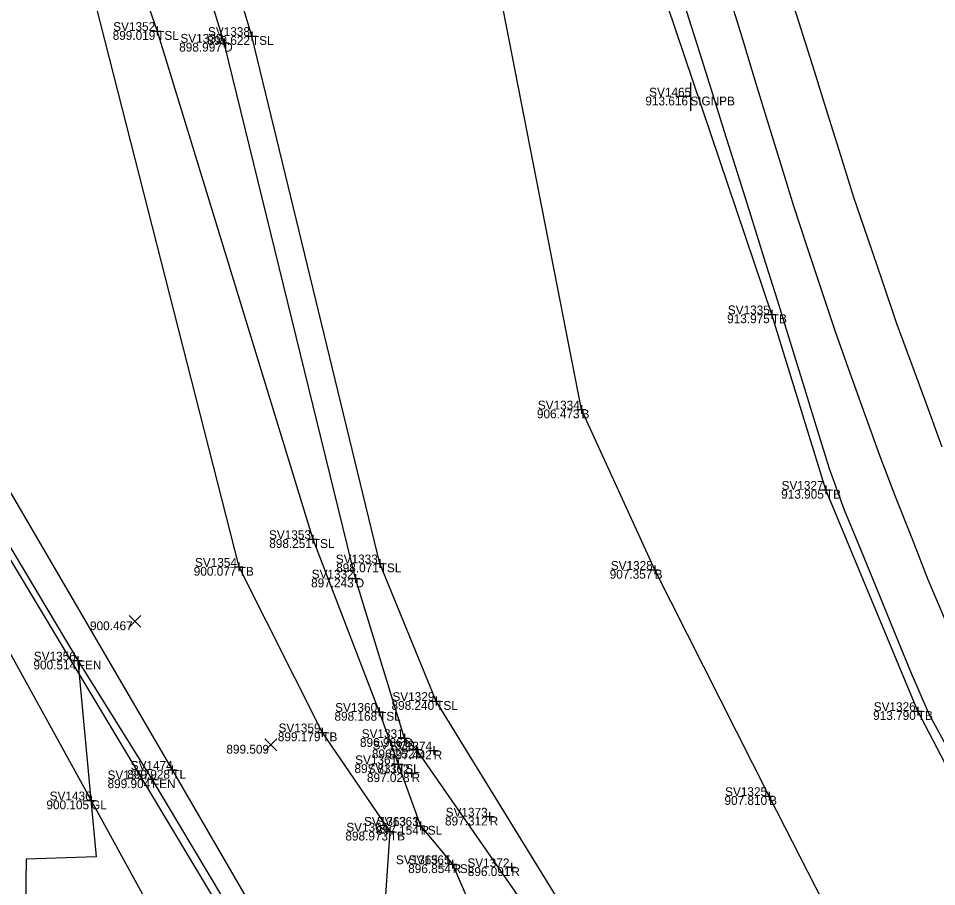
# Model space of a CAD drawing. Extents: x 1918148 to 1919797, y 624701 to 627089.
# Drawn here: x 1918830.7 to 1918934.8, y 625607.8 to 625706.2 of the extents above; entities that cross this region are included whole.
import ezdxf

# ---------------------------------------------------------------- set-up
doc = ezdxf.new("R2010")
doc.units = 0
for name, color, linetype in [('DR_X_Ditch', 7, 'Continuous'), ('DT_X_Terrain_Boundary', 7, 'Continuous'), ('Ground Shots', 7, 'Continuous'), ('PM_X_Edge_Line', 7, 'Continuous'), ('PV_X_Shoulder_Aggregate', 7, 'Continuous'), ('RD_X_Concrete_Pad', 7, 'Continuous'), ('RD_X_Fence', 7, 'Continuous'), ('SN_X_Public', 7, 'Continuous'), ('SV_X_Break_Lines', 7, 'Continuous'), ('SV_X_Random_Point', 7, 'Continuous'), ('SV_X_Shot_Marker', 7, 'Continuous'), ('SV_X_Text_Comment', 7, 'Continuous'), ('SV_X_Text_Elevation', 7, 'Continuous'), ('SV_X_Text_Name', 7, 'Continuous'), ('SV_X_Toe_of_Slope', 7, 'Continuous'), ('SV_X_Top_of_Bank', 7, 'Continuous'), ('UT_X_Gas', 7, 'Continuous'), ('UT_X_Overhead_Combined', 7, 'Continuous'), ('UT_X_Telecom', 7, 'Continuous')]:
    doc.layers.add(name, color=color, linetype=linetype)

msp = doc.modelspace()

# ---------------------------------------------------------------- linework, layer by layer
at = {"layer": 'DR_X_Ditch'}
msp.add_lwpolyline([(1918900.32, 625584.27), (1918896.98, 625591.92), (1918892.59, 625599.25), (1918875.81, 625623.37), (1918874.46, 625624.66), (1918868.91, 625642.74), (1918854.01, 625703.44), (1918836.26, 625761.36)], dxfattribs=at)
at = {"layer": 'DT_X_Terrain_Boundary'}
msp.add_lwpolyline([(1918796.76, 625701.53), (1918837.42, 625633.44), (1918839.5, 625611.2), (1918831.56, 625610.96), (1918831.45, 625603.21), (1918831.49, 625595.21), (1918831.79, 625587.3), (1918839.47, 625579.2), (1918839.49, 625571.21), (1918847.48, 625555.19), (1918855.45, 625539.21), (1918863.74, 625523.31), (1918871.72, 625515.38), (1918879.45, 625499.23)], dxfattribs=at)
at = {"layer": 'Ground Shots'}
for p, q in [((1918839.5, 625611.2), (1918839.5, 625611.2)), ((1918831.56, 625610.96), (1918831.56, 625610.96))]:
    msp.add_line(p, q, dxfattribs=at)
at = {"layer": 'PM_X_Edge_Line'}
msp.add_lwpolyline([(1918917.87, 625709.8), (1918919.37, 625705.03), (1918920.87, 625700.26), (1918922.36, 625695.49), (1918923.86, 625690.71), (1918925.36, 625685.95), (1918926.97, 625681.21), (1918928.58, 625676.48), (1918930.2, 625671.75), (1918931.92, 625667.05), (1918933.64, 625662.36), (1918935.37, 625657.67)], dxfattribs=at)
at = {"layer": 'PV_X_Shoulder_Aggregate'}
msp.add_lwpolyline([(1918936.29, 625622.98), (1918933.92, 625627.38), (1918931.93, 625631.97), (1918930.04, 625636.59), (1918928.14, 625641.22), (1918926.24, 625645.84), (1918924.34, 625650.47), (1918922.62, 625655.16), (1918921.15, 625659.94), (1918919.67, 625664.71), (1918918.2, 625669.49), (1918916.72, 625674.27), (1918915.23, 625679.04), (1918913.73, 625683.81), (1918912.23, 625688.58), (1918910.73, 625693.35), (1918909.24, 625698.12), (1918907.74, 625702.89), (1918906.24, 625707.66)], dxfattribs=at)
at = {"layer": 'RD_X_Concrete_Pad'}
msp.add_lwpolyline([(1918911.23, 625708.88), (1918912.67, 625704.1), (1918914.12, 625699.31), (1918915.59, 625694.53), (1918917.07, 625689.75), (1918918.55, 625684.98), (1918920.11, 625680.23), (1918921.69, 625675.49), (1918923.27, 625670.74), (1918924.94, 625666.03), (1918926.63, 625661.32), (1918928.32, 625656.62), (1918930.11, 625651.95), (1918931.94, 625647.3), (1918933.77, 625642.64), (1918935.73, 625638.04)], dxfattribs=at)
at = {"layer": 'RD_X_Fence'}
msp.add_lwpolyline([(1918745.79, 625786.43), (1918772.78, 625741.75), (1918796.76, 625701.53), (1918837.42, 625633.44), (1918845.82, 625619.99), (1919000.61, 625360.91)], dxfattribs=at)
at = {"layer": 'SN_X_Public'}
for p, q in [((1918906.85, 625698.94), (1918906.85, 625695.74)), ((1918906.85, 625697.34), (1918905.25, 625697.34))]:
    msp.add_line(p, q, dxfattribs=at)
at = {"layer": 'SV_X_Break_Lines'}
msp.add_lwpolyline([(1919045.66, 625427.6), (1919011.53, 625464.07), (1918983.19, 625498.78), (1918965.77, 625524.18), (1918940.24, 625565.26), (1918931.64, 625587.04), (1918915.78, 625618.09), (1918902.81, 625643.72), (1918894.51, 625661.89), (1918884.61, 625712.49), (1918865.54, 625771.79)], dxfattribs=at)
at = {"layer": 'SV_X_Random_Point'}
for p, q in [((1918843.23, 625637.22), (1918844.57, 625638.56)), ((1918843.23, 625638.56), (1918844.57, 625637.22)), ((1918858.63, 625623.23), (1918859.97, 625624.57)), ((1918858.63, 625624.57), (1918859.97, 625623.23))]:
    msp.add_line(p, q, dxfattribs=at)
at = {"layer": 'SV_X_Shot_Marker'}
for p, q in [((1918845.91, 625704.77), (1918846.91, 625704.77)), ((1918846.41, 625705.27), (1918846.41, 625704.27)), ((1918846.41, 625704.77), (1918846.41, 625704.77)), ((1918854.01, 625703.94), (1918854.01, 625702.94)), ((1918856.66, 625704.2), (1918857.66, 625704.2)), ((1918857.16, 625704.7), (1918857.16, 625703.7)), ((1918857.16, 625704.2), (1918857.16, 625704.2)), ((1918853.51, 625703.44), (1918854.51, 625703.44)), ((1918854.01, 625703.44), (1918854.01, 625703.44)), ((1918915.59, 625672.67), (1918916.59, 625672.67)), ((1918916.09, 625673.17), (1918916.09, 625672.17)), ((1918916.09, 625672.67), (1918916.09, 625672.67)), ((1918894.51, 625662.39), (1918894.51, 625661.39)), ((1918894.01, 625661.89), (1918895.01, 625661.89)), ((1918894.51, 625661.89), (1918894.51, 625661.89)), ((1918921.72, 625652.79), (1918922.72, 625652.79)), ((1918922.22, 625653.29), (1918922.22, 625652.29)), ((1918922.22, 625652.79), (1918922.22, 625652.79)), ((1918864.06, 625647.7), (1918864.06, 625646.7)), ((1918863.56, 625647.2), (1918864.56, 625647.2)), ((1918864.06, 625647.2), (1918864.06, 625647.2)), ((1918855.66, 625644.56), (1918855.66, 625643.56)), ((1918871.14, 625644.45), (1918872.14, 625644.45)), ((1918871.64, 625644.95), (1918871.64, 625643.95)), ((1918871.64, 625644.45), (1918871.64, 625644.45)), ((1918855.16, 625644.06), (1918856.16, 625644.06)), ((1918855.66, 625644.06), (1918855.66, 625644.06)), ((1918902.31, 625643.72), (1918903.31, 625643.72)), ((1918902.81, 625644.22), (1918902.81, 625643.22)), ((1918902.81, 625643.72), (1918902.81, 625643.72)), ((1918868.41, 625642.74), (1918869.41, 625642.74)), ((1918868.91, 625643.24), (1918868.91, 625642.24)), ((1918868.91, 625642.74), (1918868.91, 625642.74)), ((1918837.42, 625633.94), (1918837.42, 625632.94)), ((1918836.92, 625633.44), (1918837.92, 625633.44)), ((1918837.42, 625633.44), (1918837.42, 625633.44)), ((1918877.54, 625628.86), (1918878.54, 625628.86)), ((1918878.04, 625629.36), (1918878.04, 625628.36)), ((1918878.04, 625628.86), (1918878.04, 625628.86)), ((1918871.57, 625628.13), (1918871.57, 625627.13)), ((1918932.13, 625627.72), (1918933.13, 625627.72)), ((1918932.63, 625628.22), (1918932.63, 625627.22)), ((1918932.63, 625627.72), (1918932.63, 625627.72)), ((1918871.07, 625627.63), (1918872.07, 625627.63)), ((1918871.57, 625627.63), (1918871.57, 625627.63)), ((1918865.13, 625625.81), (1918865.13, 625624.81)), ((1918864.63, 625625.31), (1918865.63, 625625.31)), ((1918865.13, 625625.31), (1918865.13, 625625.31)), ((1918873.96, 625624.66), (1918874.96, 625624.66)), ((1918874.46, 625625.16), (1918874.46, 625624.16)), ((1918874.46, 625624.66), (1918874.46, 625624.66)), ((1918875.81, 625623.87), (1918875.81, 625622.87)), ((1918877.76, 625623.75), (1918877.76, 625622.75)), ((1918875.31, 625623.37), (1918876.31, 625623.37)), ((1918875.81, 625623.37), (1918875.81, 625623.37)), ((1918877.26, 625623.25), (1918878.26, 625623.25)), ((1918877.76, 625623.25), (1918877.76, 625623.25)), ((1918848.13, 625621.56), (1918848.13, 625620.56)), ((1918873.22, 625621.7), (1918874.22, 625621.7)), ((1918873.72, 625622.2), (1918873.72, 625621.2)), ((1918873.72, 625621.7), (1918873.72, 625621.7)), ((1918845.82, 625620.49), (1918845.82, 625619.49)), ((1918847.63, 625621.06), (1918848.63, 625621.06)), ((1918848.13, 625621.06), (1918848.13, 625621.06)), ((1918874.75, 625620.68), (1918875.75, 625620.68)), ((1918875.25, 625621.18), (1918875.25, 625620.18)), ((1918875.25, 625620.68), (1918875.25, 625620.68)), ((1918845.32, 625619.99), (1918846.32, 625619.99)), ((1918845.82, 625619.99), (1918845.82, 625619.99)), ((1918915.78, 625618.59), (1918915.78, 625617.59)), ((1918838.43, 625617.6), (1918839.43, 625617.6)), ((1918838.93, 625618.1), (1918838.93, 625617.1)), ((1918838.93, 625617.6), (1918838.93, 625617.6)), ((1918915.28, 625618.09), (1918916.28, 625618.09)), ((1918915.78, 625618.09), (1918915.78, 625618.09)), ((1918884.1, 625616.26), (1918884.1, 625615.26)), ((1918876.27, 625615.22), (1918876.27, 625614.22)), ((1918876.27, 625615.22), (1918876.27, 625614.22)), ((1918883.6, 625615.76), (1918884.6, 625615.76)), ((1918884.1, 625615.76), (1918884.1, 625615.76)), ((1918872.8, 625614.56), (1918872.8, 625613.56)), ((1918875.77, 625614.72), (1918876.77, 625614.72)), ((1918875.77, 625614.72), (1918876.77, 625614.72)), ((1918876.27, 625614.72), (1918876.27, 625614.72)), ((1918876.27, 625614.72), (1918876.27, 625614.72)), ((1918872.3, 625614.06), (1918873.3, 625614.06)), ((1918872.8, 625614.06), (1918872.8, 625614.06)), ((1918879.4, 625610.37), (1918880.4, 625610.37)), ((1918879.4, 625610.37), (1918880.4, 625610.37)), ((1918879.9, 625610.87), (1918879.9, 625609.87)), ((1918879.9, 625610.87), (1918879.9, 625609.87)), ((1918879.9, 625610.37), (1918879.9, 625610.37)), ((1918879.9, 625610.37), (1918879.9, 625610.37)), ((1918886.06, 625610.03), (1918887.06, 625610.03)), ((1918886.56, 625610.53), (1918886.56, 625609.53)), ((1918886.56, 625610.03), (1918886.56, 625610.03))]:
    msp.add_line(p, q, dxfattribs=at)
at = {"layer": 'SV_X_Toe_of_Slope'}
for points in [[(1918904.94, 625587.5), (1918897.91, 625593.83), (1918894.69, 625601.75), (1918878.04, 625628.86), (1918871.64, 625644.45), (1918857.16, 625704.2), (1918839.62, 625762.85)], [(1918827.68, 625758.54), (1918846.41, 625704.77), (1918864.06, 625647.2), (1918871.57, 625627.63), (1918873.72, 625621.7), (1918876.27, 625614.72), (1918879.9, 625610.37), (1918881.93, 625605.64), (1918886.64, 625601.99), (1918888.53, 625592.54), (1918892.5, 625587.73), (1918897.31, 625583.06)]]:
    msp.add_lwpolyline(points, dxfattribs=at)
at = {"layer": 'SV_X_Top_of_Bank'}
for points in [[(1919066.32, 625440.14), (1919029.78, 625482.47), (1919003.4, 625512.19), (1918983.32, 625538.26), (1918960.17, 625575.62), (1918948.94, 625596.56), (1918932.63, 625627.72), (1918922.22, 625652.79), (1918916.09, 625672.67), (1918901.24, 625716.64), (1918882.07, 625777.61)], [(1918817.46, 625755.24), (1918837.99, 625713.42), (1918855.66, 625644.06), (1918865.13, 625625.31), (1918872.8, 625614.06), (1918871.94, 625601.83), (1918874.31, 625585.84), (1918879.01, 625584.49), (1918882.36, 625583.6), (1918884.27, 625576.06)]]:
    msp.add_lwpolyline(points, dxfattribs=at)
at = {"layer": 'UT_X_Gas'}
msp.add_lwpolyline([(1918759.17, 625917.08), (1918754.31, 625900.24), (1918749.45, 625846.76), (1918748.46, 625829), (1918743.94, 625797.46), (1918743.01, 625773.57), (1918765.83, 625740.86), (1918795.68, 625692.78), (1918822.43, 625647.51), (1918838.93, 625617.6), (1918864.37, 625571.21), (1918888.36, 625525.76), (1918914.14, 625478.38), (1918935.19, 625439.32), (1918956.47, 625399.66), (1918975.3, 625371.47), (1919011.93, 625334.48), (1919018.03, 625313.57)], dxfattribs=at)
at = {"layer": 'UT_X_Overhead_Combined'}
msp.add_lwpolyline([(1918749.03, 625800.12), (1918759.42, 625761.9), (1918898.02, 625531.27), (1919016.4, 625331.43)], dxfattribs=at)
at = {"layer": 'UT_X_Telecom'}
msp.add_lwpolyline([(1918746.05, 625787.64), (1918759.45, 625770.26), (1918759.45, 625770.26), (1918782.32, 625734.01), (1918799.1, 625706.16), (1918807.73, 625686.59), (1918828.09, 625655.33), (1918848.13, 625621.06), (1918864.02, 625593.65)], dxfattribs=at)

# ---------------------------------------------------------------- texts
at = {"layer": 'SV_X_Text_Comment'}
for s, p in [('TSL', (1918846.41, 625703.77)), ('TSL', (1918857.16, 625703.2)), ('D', (1918854.01, 625702.44)), ('SIGNPB', (1918906.85, 625696.34)), ('TB', (1918916.09, 625671.67)), ('B', (1918894.51, 625660.89)), ('TB', (1918922.22, 625651.79)), ('TSL', (1918864.06, 625646.2)), ('TSL', (1918871.64, 625643.45)), ('TB', (1918855.66, 625643.06)), ('B', (1918902.81, 625642.72)), ('D', (1918868.91, 625641.74)), ('FEN', (1918837.42, 625632.44)), ('TSL', (1918878.04, 625627.86)), ('TB', (1918932.63, 625626.72)), ('TSL', (1918871.57, 625626.63)), ('TB', (1918865.13, 625624.31)), ('D', (1918874.46, 625623.66)), ('D', (1918875.81, 625622.37)), ('R', (1918877.76, 625622.25)), ('TSL', (1918873.72, 625620.7)), ('TL', (1918848.13, 625620.06)), ('R', (1918875.25, 625619.68)), ('FEN', (1918845.82, 625618.99)), ('GL', (1918838.93, 625616.6)), ('B', (1918915.78, 625617.09)), ('R', (1918884.1, 625614.76)), ('TSL', (1918876.27, 625613.72)), ('R', (1918876.27, 625613.72)), ('TB', (1918872.8, 625613.06)), ('TSL', (1918879.9, 625609.37)), ('R', (1918879.9, 625609.37)), ('R', (1918886.56, 625609.03))]:
    msp.add_text(s, height=1, dxfattribs=at).set_placement(p)
at = {"layer": 'SV_X_Text_Elevation'}
for s, p in [('899.019', (1918841.37, 625703.77)), ('899.622', (1918852.1, 625703.2)), ('898.997', (1918848.91, 625702.44)), ('913.616', (1918901.75, 625696.34)), ('913.975', (1918911.02, 625671.67)), ('906.473', (1918889.46, 625660.89)), ('913.905', (1918917.15, 625651.79)), ('898.251', (1918859.12, 625646.2)), ('898.071', (1918866.7, 625643.45)), ('900.077', (1918850.56, 625643.06)), ('907.357', (1918897.71, 625642.72)), ('897.243', (1918863.86, 625641.74)), ('900.467', (1918838.8, 625636.89)), ('900.514', (1918832.39, 625632.44)), ('898.240', (1918872.98, 625627.86)), ('913.790', (1918927.57, 625626.72)), ('898.168', (1918866.51, 625626.63)), ('899.179', (1918860.09, 625624.31)), ('896.986', (1918869.4, 625623.66)), ('899.509', (1918854.26, 625622.9)), ('896.252', (1918870.75, 625622.37)), ('897.442', (1918872.7, 625622.25)), ('897.831', (1918868.78, 625620.7)), ('899.928', (1918843.03, 625620.06)), ('897.028', (1918870.19, 625619.68)), ('899.904', (1918840.79, 625618.99)), ('900.105', (1918833.86, 625616.6)), ('907.810', (1918910.72, 625617.09)), ('897.312', (1918879.04, 625614.76)), ('897.154', (1918871.24, 625613.72)), ('897.154', (1918871.24, 625613.72)), ('898.973', (1918867.75, 625613.06)), ('896.854', (1918874.87, 625609.37)), ('896.854', (1918874.87, 625609.37)), ('896.091', (1918881.62, 625609.03))]:
    msp.add_text(s, height=1, dxfattribs=at).set_placement(p)
at = {"layer": 'SV_X_Text_Name'}
for s, p in [('SV1352', (1918841.43, 625704.77)), ('SV1338', (1918852.17, 625704.2)), ('SV1339', (1918849.05, 625703.44)), ('SV1465', (1918902.18, 625697.34)), ('SV1335', (1918911.1, 625672.67)), ('SV1334', (1918889.56, 625661.89)), ('SV1327', (1918917.19, 625652.79)), ('SV1353', (1918859.09, 625647.2)), ('SV1333', (1918866.66, 625644.45)), ('SV1354', (1918850.7, 625644.06)), ('SV1328', (1918897.83, 625643.72)), ('SV1332', (1918863.93, 625642.74)), ('SV1356', (1918832.43, 625633.44)), ('SV1329', (1918873.08, 625628.86)), ('SV1326', (1918927.64, 625627.72)), ('SV1360', (1918866.59, 625627.63)), ('SV1359', (1918860.17, 625625.31)), ('SV1331', (1918869.6, 625624.66)), ('SV1330', (1918870.83, 625623.37)), ('SV1374', (1918872.81, 625623.25)), ('SV1361', (1918868.86, 625621.7)), ('SV1474', (1918843.41, 625621.06)), ('SV1362', (1918870.27, 625620.68)), ('SV1357', (1918840.79, 625619.99)), ('SV1436', (1918834.23, 625617.6)), ('SV1325', (1918910.79, 625618.09)), ('SV1373', (1918879.12, 625615.76)), ('SV1363_1', (1918869.86, 625614.72)), ('SV1363', (1918871.3, 625614.72)), ('SV1364', (1918867.85, 625614.06)), ('SV1365_1', (1918873.48, 625610.37)), ('SV1365', (1918874.91, 625610.37)), ('SV1372', (1918881.58, 625610.03))]:
    msp.add_text(s, height=1, dxfattribs=at).set_placement(p)

doc.saveas('drawing.dxf')
